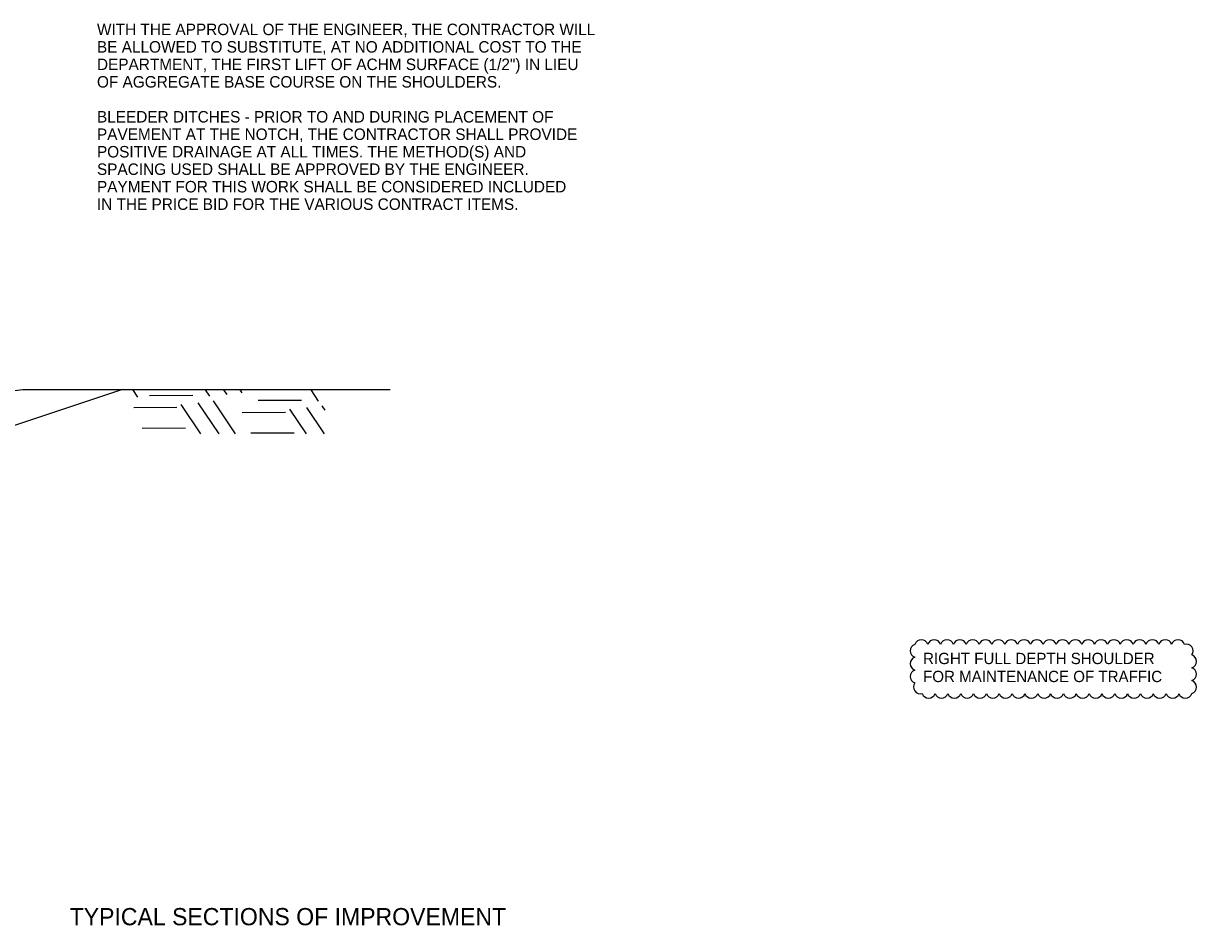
# Model space of a CAD drawing. Extents: x 1398183 to 1398373, y 1967240 to 1968889.
# Drawn here: x 1398305.8 to 1398367.1, y 1967705.6 to 1967752.7 of the extents above; entities that cross this region are included whole.
import ezdxf

# ---------------------------------------------------------------- set-up
doc = ezdxf.new("R2010")
doc.units = 0
for name, color, linetype in [('19', 7, 'Continuous'), ('42', 7, 'Continuous'), ('60', 7, 'Continuous'), ('9', 7, 'Continuous')]:
    doc.layers.add(name, color=color, linetype=linetype)

msp = doc.modelspace()

# ---------------------------------------------------------------- linework, layer by layer
at = {"layer": '19'}
msp.add_line((1398310.965, 1967733.585), (1398294.374, 1967728.054), dxfattribs=at)
msp.add_lwpolyline([(1398260.14, 1967730.516), (1398273.709, 1967725.611), (1398287.825, 1967731.321), (1398305.763, 1967733.585), (1398324.954, 1967733.585)], dxfattribs=at)
for centre, radius, start, end in [((1398352.704, 1967720.163), 0.352, 17.5, 162.5), ((1398353.375, 1967720.163), 0.352, 17.5, 162.5), ((1398354.045, 1967720.163), 0.352, 17.5, 162.5), ((1398354.716, 1967720.163), 0.352, 17.5, 162.5), ((1398355.387, 1967720.163), 0.352, 17.5, 162.5), ((1398356.057, 1967720.163), 0.352, 17.5, 162.5), ((1398356.728, 1967720.163), 0.352, 17.5, 162.5), ((1398357.399, 1967720.163), 0.352, 17.5, 162.5), ((1398358.07, 1967720.163), 0.352, 17.5, 162.5), ((1398358.74, 1967720.163), 0.352, 17.5, 162.5), ((1398359.411, 1967720.163), 0.352, 17.5, 162.5), ((1398360.082, 1967720.163), 0.352, 17.5, 162.5), ((1398360.752, 1967720.163), 0.352, 17.5, 162.5), ((1398361.423, 1967720.163), 0.352, 17.5, 162.5), ((1398362.094, 1967720.163), 0.352, 17.5, 162.5), ((1398362.764, 1967720.163), 0.352, 17.5, 162.5), ((1398363.435, 1967720.163), 0.352, 17.5, 162.5), ((1398364.106, 1967720.163), 0.352, 17.5, 162.5), ((1398364.776, 1967720.163), 0.352, 17.5, 162.5), ((1398365.447, 1967720.163), 0.352, 17.5, 162.5), ((1398366.118, 1967720.163), 0.352, 17.5, 162.5), ((1398352.474, 1967719.934), 0.352, 107.5, 252.5), ((1398366.558, 1967719.934), 0.351, 322.43874, 107.43874), ((1398366.731, 1967719.384), 0.352, 287.5, 72.5), ((1398352.474, 1967719.263), 0.352, 107.5, 252.5), ((1398352.474, 1967718.592), 0.352, 107.5, 252.5), ((1398366.731, 1967718.714), 0.352, 287.5, 72.5), ((1398352.647, 1967718.043), 0.351, 142.43874, 287.43874), ((1398366.731, 1967718.043), 0.352, 287.5, 72.5), ((1398353.088, 1967717.813), 0.352, 197.5, 342.5), ((1398353.759, 1967717.813), 0.352, 197.5, 342.5), ((1398354.429, 1967717.813), 0.352, 197.5, 342.5), ((1398355.1, 1967717.813), 0.352, 197.5, 342.5), ((1398355.771, 1967717.813), 0.352, 197.5, 342.5), ((1398356.441, 1967717.813), 0.352, 197.5, 342.5), ((1398357.112, 1967717.813), 0.352, 197.5, 342.5), ((1398357.783, 1967717.813), 0.352, 197.5, 342.5), ((1398358.453, 1967717.813), 0.352, 197.5, 342.5), ((1398359.124, 1967717.813), 0.352, 197.5, 342.5), ((1398359.795, 1967717.813), 0.352, 197.5, 342.5), ((1398360.465, 1967717.813), 0.352, 197.5, 342.5), ((1398361.136, 1967717.813), 0.352, 197.5, 342.5), ((1398361.807, 1967717.813), 0.352, 197.5, 342.5), ((1398362.478, 1967717.813), 0.352, 197.5, 342.5), ((1398363.148, 1967717.813), 0.352, 197.5, 342.5), ((1398363.819, 1967717.813), 0.352, 197.5, 342.5), ((1398364.49, 1967717.813), 0.352, 197.5, 342.5), ((1398365.16, 1967717.813), 0.352, 197.5, 342.5), ((1398365.831, 1967717.813), 0.352, 197.5, 342.5), ((1398366.502, 1967717.813), 0.352, 197.5, 342.5)]:
    msp.add_arc(centre, radius, start, end, dxfattribs=at)
at = {"layer": '9'}
for p, q in [((1398311.776, 1967733.175), (1398311.51, 1967733.571)), ((1398314.649, 1967733.263), (1398312.387, 1967733.248)), ((1398315.539, 1967733.224), (1398315.311, 1967733.564)), ((1398316.429, 1967733.315), (1398316.263, 1967733.562)), ((1398317.227, 1967733.407), (1398317.123, 1967733.561)), ((1398321.212, 1967732.973), (1398320.821, 1967733.554)), ((1398313.814, 1967732.634), (1398311.552, 1967732.619)), ((1398315.065, 1967731.27), (1398314.037, 1967732.8)), ((1398316.017, 1967731.268), (1398314.927, 1967732.891)), ((1398316.877, 1967731.267), (1398315.724, 1967732.983)), ((1398320.322, 1967733.011), (1398318.06, 1967732.997)), ((1398321.528, 1967731.258), (1398320.6, 1967732.64)), ((1398321.552, 1967732.501), (1398321.397, 1967732.731)), ((1398319.487, 1967732.382), (1398317.225, 1967732.368)), ((1398320.576, 1967731.26), (1398319.709, 1967732.549)), ((1398314.257, 1967731.557), (1398311.995, 1967731.543)), ((1398319.93, 1967731.306), (1398317.668, 1967731.291))]:
    msp.add_line(p, q, dxfattribs=at)

# ---------------------------------------------------------------- texts
at = {"layer": '19'}
for s, p in [('WITH THE APPROVAL OF THE ENGINEER, THE CONTRACTOR WILL', (1398309.634, 1967752.083)), ('BE ALLOWED TO SUBSTITUTE, AT NO ADDITIONAL COST TO THE', (1398309.634, 1967751.17)), ('DEPARTMENT, THE FIRST LIFT OF ACHM SURFACE (1/2") IN LIEU', (1398309.634, 1967750.258)), ('OF AGGREGATE BASE COURSE ON THE SHOULDERS.', (1398309.634, 1967749.345)), ('BLEEDER DITCHES - PRIOR TO AND DURING PLACEMENT OF', (1398309.634, 1967747.52)), ('PAVEMENT AT THE NOTCH, THE CONTRACTOR SHALL PROVIDE', (1398309.634, 1967746.608)), ('POSITIVE DRAINAGE AT ALL TIMES. THE METHOD(S) AND', (1398309.634, 1967745.695)), ('SPACING USED SHALL BE APPROVED BY THE ENGINEER.', (1398309.634, 1967744.783)), ('PAYMENT FOR THIS WORK SHALL BE CONSIDERED INCLUDED', (1398309.634, 1967743.87)), ('IN THE PRICE BID FOR THE VARIOUS CONTRACT ITEMS.', (1398309.634, 1967742.958))]:
    msp.add_text(s, height=0.6, dxfattribs=at).set_placement(p)
at = {"layer": '42'}
for s, p in [('RIGHT FULL DEPTH SHOULDER', (1398352.795, 1967719.24)), ('FOR MAINTENANCE OF TRAFFIC', (1398352.795, 1967718.3))]:
    msp.add_text(s, height=0.59001, rotation=360, dxfattribs=at).set_placement(p)
at = {"layer": '60'}
msp.add_text('TYPICAL SECTIONS OF IMPROVEMENT', height=0.9, dxfattribs=at).set_placement((1398308.207, 1967705.603))

doc.saveas('drawing.dxf')
